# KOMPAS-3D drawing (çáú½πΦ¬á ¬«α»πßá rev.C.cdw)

Views: Вид 1, Спереди
Referenced files in D:\_Downloads\: Заглушка корпуса rev.C.m3d
Referenced files in E:\: Чертеж Заглушка корпуса.cdw
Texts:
  Im2
  Заглушка корпуса
Dimensions and other numbers on the sheet: 15; 16,5; 8; 13; 164; 57; 10,5; 26; 12,5; 25; 19,5; 34,5; 25,5; 40,5; 22,5; 9; 3,1; 10; 7; 33,5; 28; 1,75; 20,5; 4; 31,5; 36,25; 1:1; 0,06; 1; 0; 2; 3; 5; 6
